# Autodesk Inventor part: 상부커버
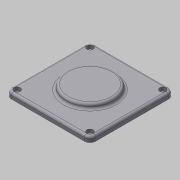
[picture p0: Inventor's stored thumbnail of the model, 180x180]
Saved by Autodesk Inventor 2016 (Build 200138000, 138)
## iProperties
Created: 2018-09
Part Number: 상부커버
Document SubType Name: Modeling
Density: 2.71 g/cm^3
Material: 알루미늄 6061
Mass: 249.405 g
Surface Area: 254.001 cm^2
Volume: 92.0315 cm^3
Appearance: 알루미늄 - 평지
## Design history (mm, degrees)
sketch "스케치5"
  geometry: L1 (-52.5, -52.5)-(52.5, -52.5); L2 (52.5, -52.5)-(52.5, 52.5); L3 (52.5, 52.5)-(-52.5, 52.5); L4 (-52.5, 52.5)-(-52.5, -52.5); L5 (-52.5, -52.5)-(52.5, 52.5); L6 (52.5, -52.5)-(-52.5, 52.5); 1 further point
  constraints: 12 end point, 2 midpoint, 2 parallel, 1 horizontal, 1 perpendicular
  dimensions: "d35" = 105 distance of L3.end L2.end; "d36" = 105 distance of L2.end L1.end
extrude "돌출4" new body sketch "스케치5" distance "d37" = 7; taper "d38" = 0 deg
fillet "모깎기4" dims "d39" = 7
sketch "스케치2"
  geometry: C1 r 30 at (0, 0); 2 further points
  constraints: 2 coincident, 1 centre point
  dimensions: "d4" = 60 diameter of C1
extrude "돌출3" join sketch "스케치2" distance "d5" = 6; taper "d6" = 0 deg
fillet "모깎기1" dims "d7" = 3
sketch "스케치4"
  geometry: L1 (52.5, -45.5)-(52.5, 45.5) reference; L2 (-45.5, -52.5)-(45.5, -52.5) reference; L3 (-52.5, 45.5)-(-52.5, -45.5) reference; L4 (45.5, 52.5)-(-45.5, 52.5) reference; A1 r 7 centre (45.5, 45.5) between (52.5, 45.5) and (45.5, 52.5) reference; A2 r 7 centre (45.5, -45.5) between (45.5, -52.5) and (52.5, -45.5) reference; A3 r 7 centre (-45.5, -45.5) between (-52.5, -45.5) and (-45.5, -52.5) reference; A4 r 7 centre (-45.5, 45.5) between (-45.5, 52.5) and (-52.5, 45.5) reference; 4 further points
  constraints: 4 coincident
hole "구멍3" sketch "스케치4" at (-45.5, 45.5), (-45.5, -45.5), (45.5, -45.5), (45.5, 45.5) diameter "d43" = 4.5; stored, may be unused: countersink angle "d47" = 90 deg, drill point angle "d49" = 118 deg; dims "d44" = 6, "d45" = 8, "d46" = 4.4, "d48" = 8
fillet "모깎기3" dims "d19" = 3
node "솔리드1"
node "솔리드2"
node "투영된 루프2"
